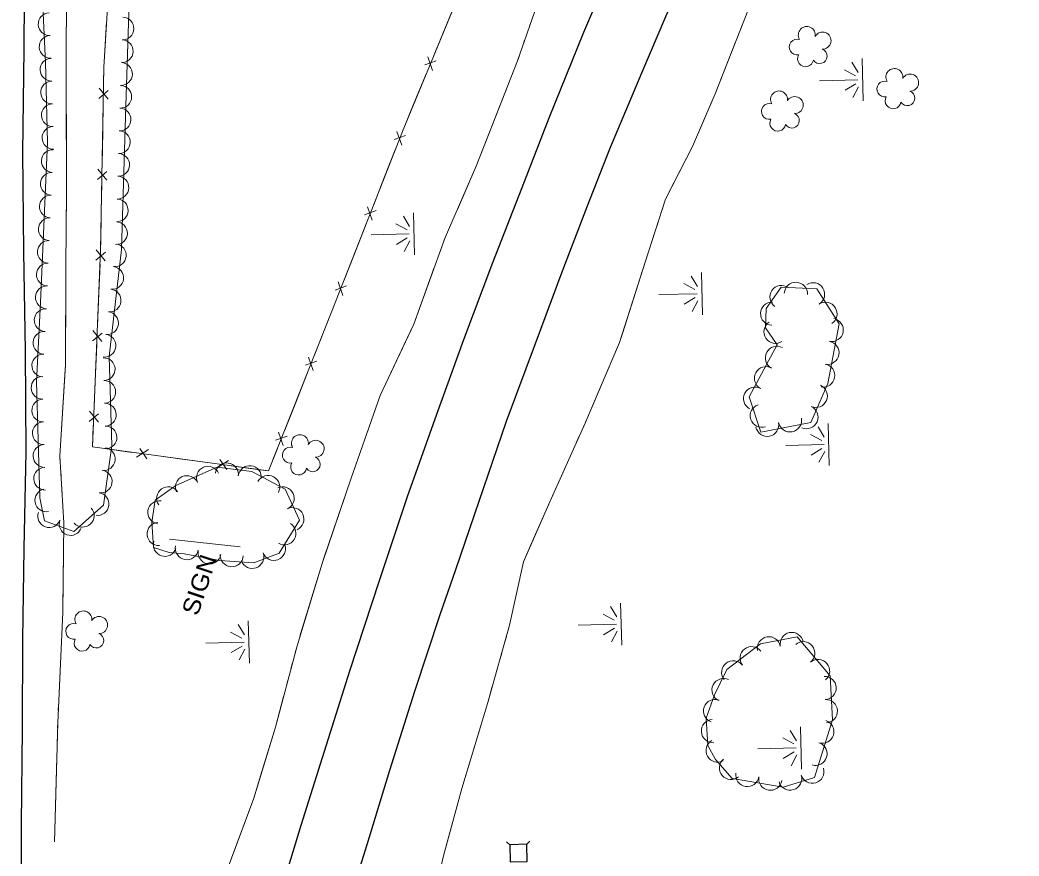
# Model space of a CAD drawing. Extents: x 296527 to 298902, y 45711 to 46924.
# Drawn here: x 297707.6 to 298057.5, y 46436.3 to 46729.1 of the extents above; entities that cross this region are included whole.
import ezdxf

# ---------------------------------------------------------------- set-up
doc = ezdxf.new("R2010")
doc.units = 0
doc.header["$LTSCALE"] = 2.4
for name, color, linetype, lineweight in [('11', 7, 'Continuous', 25), ('14', 7, 'Continuous', 13), ('15', 7, 'Continuous', 13), ('18', 7, 'Continuous', 13), ('19', 7, 'Continuous', 13), ('21', 7, 'Continuous', 25)]:
    doc.layers.add(name, color=color, linetype=linetype, lineweight=lineweight)

msp = doc.modelspace()

# ---------------------------------------------------------------- linework, layer by layer
at = {"layer": '11'}
for points in [[(297708.054, 46412.102), (297708.117, 46447.507), (297708.458, 46480.899), (297708.518, 46512.123), (297709.002, 46543.958), (297709.761, 46577.896), (297709.478, 46613.197), (297708.972, 46647.846), (297708.569, 46682.607), (297709.017, 46718.762), (297709.283, 46754.715), (297709.666, 46803.389), (297708.727, 46849.227), (297708.272, 46892.372), (297707.575, 46911.798)], [(297797.637, 46419.407), (297806.038, 46447.108), (297823.092, 46501.139), (297833.508, 46532.828), (297843.333, 46562.228), (297853.578, 46590.979), (297863.061, 46617.192), (297873.203, 46644.121), (297883.41, 46670.443), (297892.882, 46694.741), (297905.062, 46724.82), (297915.884, 46750.233), (297925.772, 46772.377), (297936.243, 46795.47), (297946.994, 46818.695), (297958.748, 46842.839), (297969.032, 46863.808), (297980.865, 46887.359), (297993.929, 46912.343)], [(297820.298, 46412.015), (297829.138, 46440.368), (297837.156, 46466.412), (297845.87, 46494.028), (297854.78, 46520.851), (297860.274, 46536.633), (297868.345, 46560.521), (297877.908, 46588.617), (297888.074, 46615.761), (297897.508, 46640.842), (297906.311, 46664.015), (297914.149, 46683.92), (297925.308, 46710.547), (297936.475, 46736.675), (297947.217, 46761.093), (297957.424, 46783.747), (297966.64, 46803.53), (297977.44, 46826.166), (297989.604, 46851.228), (298001.839, 46875.002), (298013.165, 46896.864), (298019.649, 46909.369)]]:
    msp.add_lwpolyline(points, dxfattribs=at)
at = {"layer": '14'}
msp.add_line((297759.966, 46547.257), (297784.646, 46544.522), dxfattribs=at)
at = {"layer": '15'}
for p, q in [((297860.726, 46736.553), (297856.338, 46725.929)), ((297737.293, 46718.32), (297737.912, 46728.41)), ((297856.338, 46725.929), (297852.478, 46716.586)), ((297853.37, 46714.756), (297849.311, 46713.362)), ((297850.397, 46716.171), (297851.995, 46711.428)), ((297849.927, 46710.409), (297845.538, 46699.785)), ((297735.224, 46701.532), (297738.492, 46704.315)), ((297738.509, 46701.303), (297735.286, 46705.133)), ((297736.549, 46690.048), (297736.723, 46700.156)), ((297736.35, 46678.555), (297736.549, 46690.048)), ((297842.606, 46688.628), (297838.572, 46687.16)), ((297839.608, 46689.989), (297841.291, 46685.275)), ((297839.241, 46684.219), (297835.045, 46673.519)), ((297734.735, 46673.25), (297738.004, 46676.033)), ((297738.021, 46673.02), (297734.798, 46676.851)), ((297736.06, 46661.765), (297736.235, 46671.873)), ((297835.045, 46673.519), (297831.354, 46664.107)), ((297735.862, 46650.273), (297736.06, 46661.765)), ((297832.278, 46662.294), (297828.245, 46660.827)), ((297829.28, 46663.655), (297830.964, 46658.941)), ((297828.914, 46657.886), (297824.717, 46647.185)), ((297734.162, 46645.008), (297737.498, 46647.709)), ((297737.44, 46644.697), (297734.313, 46648.606)), ((297824.717, 46647.185), (297821.026, 46637.773)), ((297735.202, 46633.494), (297735.627, 46643.595)), ((297818.952, 46637.322), (297820.636, 46632.608)), ((297734.719, 46622.01), (297735.202, 46633.494)), ((297821.951, 46635.96), (297817.917, 46634.493)), ((297732.974, 46616.746), (297736.31, 46619.447)), ((297736.252, 46616.436), (297733.125, 46620.344)), ((297814.365, 46620.861), (297810.638, 46611.464)), ((297734.014, 46605.233), (297734.439, 46615.333)), ((297811.556, 46609.647), (297807.516, 46608.195)), ((297808.563, 46611.02), (297810.228, 46606.299)), ((297733.531, 46593.748), (297734.014, 46605.233)), ((297808.174, 46605.252), (297803.936, 46594.567)), ((297803.936, 46594.567), (297800.209, 46585.17)), ((297731.786, 46588.485), (297735.122, 46591.186)), ((297735.064, 46588.174), (297731.937, 46592.083)), ((297798.133, 46584.726), (297799.799, 46580.006)), ((297801.127, 46583.353), (297797.087, 46581.901)), ((297746.894, 46577.666), (297735.505, 46579.213)), ((297752.587, 46578.675), (297748.405, 46575.924)), ((297751.973, 46575.439), (297749.594, 46579.011)), ((297763.534, 46575.406), (297753.516, 46576.766)), ((297774.923, 46573.859), (297763.534, 46575.406)), ((297780.616, 46574.867), (297776.434, 46572.117)), ((297780.002, 46571.632), (297777.623, 46575.204)), ((297791.563, 46571.599), (297781.545, 46572.959))]:
    msp.add_line(p, q, dxfattribs=at)
for points in [[(297934.044, 46907.735), (297918.048, 46878.585), (297891.783, 46819.963), (297869.421, 46757.602), (297841.737, 46690.583), (297816.848, 46627.12), (297794.659, 46571.178), (297732.935, 46579.562), (297735.83, 46648.429), (297736.937, 46712.527), (297742.759, 46807.329), (297763.72, 46870.169), (297779.778, 46909.61)], [(297736.839, 46706.837), (297736.937, 46712.527), (297737.293, 46718.32)], [(297845.538, 46699.785), (297841.737, 46690.583), (297841.681, 46690.441)], [(297818.586, 46631.552), (297816.848, 46627.12), (297814.365, 46620.861)], [(297735.505, 46579.213), (297732.935, 46579.562), (297733.251, 46587.072)], [(297797.745, 46578.958), (297794.659, 46571.178), (297791.563, 46571.599)]]:
    msp.add_lwpolyline(points, dxfattribs=at)
at = {"layer": '18'}
msp.add_lwpolyline([(297715.157, 46743.741), (297716.466, 46714.217), (297717.27, 46686.227), (297714.814, 46630.091), (297713.348, 46602.368), (297714.48, 46561.723), (297716.124, 46553.675), (297726.458, 46549.955), (297736.806, 46559.159), (297739.698, 46580.012), (297738.839, 46611.176), (297743.109, 46648.653), (297744.694, 46699.054), (297746.756, 46764.188)], dxfattribs=at)
for points in [[(297968.874, 46608.203), (297962.933, 46597.057), (297967.043, 46584.695), (297984.533, 46588.145), (297990.494, 46601.722), (297994.426, 46622.654), (297986.667, 46634.881), (297974.141, 46635.559), (297968.92, 46628.084), (297968.711, 46621.238), (297972.702, 46615.306)], [(297777.565, 46539.807), (297789.485, 46539.001), (297798.391, 46542.316), (297805.491, 46553.88), (297800.419, 46564.758), (297788.808, 46570.987), (297776.645, 46572.449), (297762.2, 46566.067), (297754.932, 46560.969), (297753.712, 46553.163), (297754.359, 46544.352), (297759.819, 46542.573), (297765.037, 46542.16)], [(297965.982, 46461.948), (297974.902, 46460.469), (297985.848, 46463.85), (297992.08, 46484.028), (297991.285, 46499.409), (297979.802, 46513.094), (297966.908, 46510.63), (297955.126, 46501.583), (297950.792, 46492.764), (297947.836, 46484.534), (297948.487, 46474.959), (297951.182, 46470.162), (297956.999, 46463.433)]]:
    msp.add_lwpolyline(points, close=True, dxfattribs=at)
for centre, radius, start, end in [((297717.959, 46727.594), 3.982, 92.54631, 272.53099), ((297743.464, 46726.059), 3.982, 268.19441, 88.17909), ((297718.312, 46719.639), 3.982, 92.54631, 272.53099), ((297983.135, 46723.798), 2.974, 349.94487, 211.17875), ((297988.651, 46721.838), 2.975, 267.59569, 150.56896), ((297743.212, 46718.1), 3.982, 268.19441, 88.17909), ((297979.775, 46719.604), 2.777, 72.91576, 280.68875), ((297982.691, 46715.467), 2.783, 149.59278, 350.60382), ((297987.644, 46716.408), 2.611, 212.30092, 70.23353), ((297718.625, 46711.65), 3.982, 91.65301, 271.63768), ((297742.96, 46710.142), 3.982, 268.19441, 88.17909), ((298013.814, 46709.084), 2.974, 349.94487, 211.17875), ((298019.33, 46707.124), 2.975, 267.59569, 150.56896), ((297718.853, 46703.691), 3.982, 91.65301, 271.63768), ((297742.708, 46702.183), 3.982, 268.19441, 88.17909), ((298010.454, 46704.89), 2.777, 72.91576, 280.68875), ((297973.398, 46701.232), 2.974, 349.94487, 211.17875), ((298018.323, 46701.694), 2.611, 212.30092, 70.23353), ((297719.082, 46695.731), 3.982, 91.65301, 271.63768), ((297970.038, 46697.038), 2.777, 72.91576, 280.68875), ((297978.914, 46699.272), 2.975, 267.59569, 150.56896), ((298013.37, 46700.753), 2.783, 149.59278, 350.60382), ((297742.457, 46694.224), 3.982, 268.20643, 88.19111), ((297977.907, 46693.842), 2.611, 212.30092, 70.23353), ((297972.954, 46692.901), 2.783, 149.59278, 350.60382), ((297719.311, 46687.772), 3.982, 91.65301, 271.63768), ((297742.207, 46686.265), 3.982, 268.20643, 88.19111), ((297719.069, 46679.665), 3.982, 87.50252, 267.48719), ((297741.956, 46678.306), 3.982, 268.20643, 88.19111), ((297718.721, 46671.71), 3.982, 87.50252, 267.48719), ((297741.706, 46670.347), 3.982, 268.20643, 88.19111), ((297718.373, 46663.755), 3.982, 87.50252, 267.48719), ((297741.456, 46662.389), 3.982, 268.20643, 88.19111), ((297718.025, 46655.8), 3.982, 87.50252, 267.48719), ((297741.206, 46654.43), 3.982, 268.20643, 88.19111), ((297717.677, 46647.845), 3.982, 87.50252, 267.48719), ((297740.784, 46646.655), 3.982, 263.50761, 83.49229), ((297717.329, 46639.89), 3.982, 87.50252, 267.48719), ((297739.882, 46638.743), 3.982, 263.50761, 83.49229), ((297974.271, 46632.04), 4.054, 55.07484, 235.05952), ((297979.315, 46633.154), 4.054, 356.90941, 176.89409), ((297985.336, 46633.019), 4.054, 302.40602, 122.3907), ((297716.981, 46631.935), 3.982, 87.50252, 267.48719), ((297738.981, 46630.832), 3.982, 263.50761, 83.49229), ((297970.986, 46626.22), 4.054, 88.25904, 268.24371), ((297989.68, 46626.174), 4.054, 302.40602, 122.3907), ((297716.577, 46623.963), 3.982, 86.98066, 266.96534), ((297738.08, 46622.92), 3.982, 263.50761, 83.49229), ((297972.179, 46619.885), 4.054, 123.94, 303.92467), ((297991.862, 46620.498), 4.054, 259.36884, 79.35351), ((297716.156, 46616.012), 3.982, 86.98066, 266.96534), ((297737.178, 46615.009), 3.982, 263.50761, 83.49229), ((297990.365, 46612.53), 4.054, 259.36884, 79.35351), ((297715.736, 46608.06), 3.982, 86.98066, 266.96534), ((297972.665, 46610.764), 4.054, 61.68623, 241.6709), ((297736.875, 46606.778), 3.982, 271.58656, 91.57123), ((297988.869, 46604.562), 4.054, 259.36884, 79.35351), ((297968.84, 46603.627), 4.054, 61.94932, 241.93399), ((297715.491, 46600.274), 3.982, 91.60299, 271.58767), ((297737.095, 46598.818), 3.982, 271.58656, 91.57123), ((297986.294, 46597.433), 4.054, 246.30372, 66.2884), ((297965.026, 46596.473), 4.054, 61.94932, 241.93399), ((297715.713, 46592.315), 3.982, 91.60299, 271.58767), ((297737.314, 46590.858), 3.982, 271.58656, 91.57123), ((297967.356, 46590.479), 4.054, 108.39811, 288.38278), ((297983.034, 46590.01), 4.054, 246.30372, 66.2884), ((297715.935, 46584.355), 3.982, 91.60299, 271.58767), ((297969.299, 46587.303), 4.054, 191.16632, 11.151), ((297977.253, 46588.872), 4.054, 191.16632, 11.151), ((297737.534, 46582.899), 3.982, 271.58656, 91.57123), ((297805.606, 46580.873), 2.974, 349.94487, 211.17875), ((297716.156, 46576.395), 3.982, 91.60299, 271.58767), ((297811.122, 46578.913), 2.975, 267.59569, 150.56896), ((297736.944, 46575.328), 3.982, 262.11196, 82.09663), ((297802.246, 46576.679), 2.777, 72.91576, 280.68875), ((297780.026, 46569.909), 4.047, 353.15356, 173.13824), ((297805.162, 46572.542), 2.783, 149.59278, 350.60382), ((297810.115, 46573.483), 2.611, 212.30092, 70.23353), ((297716.378, 46568.436), 3.982, 91.60299, 271.58767), ((297735.851, 46567.441), 3.982, 262.11196, 82.09663), ((297773.446, 46568.72), 4.047, 23.84416, 203.82884), ((297788.061, 46568.944), 4.047, 353.15356, 173.13824), ((297794.499, 46565.53), 4.047, 331.79526, 151.77994), ((297766.043, 46565.449), 4.047, 23.84416, 203.82884), ((297716.783, 46560.861), 3.982, 101.55288, 281.53756), ((297734.757, 46559.554), 3.982, 262.11196, 82.09663), ((297759.465, 46561.561), 4.047, 35.05467, 215.03935), ((297799.56, 46561.587), 4.047, 295.00552, 114.9902), ((297756.401, 46556.648), 4.047, 81.12476, 261.10944), ((297717.821, 46555.279), 3.982, 160.20996, 340.19464), ((297729.553, 46555.497), 3.982, 221.65907, 41.64374), ((297802.98, 46554.252), 4.047, 295.00552, 114.9902), ((297725.313, 46552.582), 3.982, 160.20996, 340.19464), ((297756.134, 46549.095), 4.047, 94.20741, 274.19208), ((297800.183, 46549.283), 4.047, 238.4588, 58.44348), ((297758.336, 46545.284), 4.047, 161.9608, 341.94548), ((297796.511, 46543.876), 4.047, 200.42398, 20.40866), ((297766.026, 46544.129), 4.047, 169.37034, 349.35501), ((297773.98, 46542.636), 4.047, 169.37034, 349.35501), ((297781.746, 46541.647), 4.047, 176.13936, 356.12403), ((297788.927, 46541.053), 4.047, 200.42398, 20.40866), ((297729.769, 46519.16), 2.974, 349.94487, 211.17875), ((297726.409, 46514.966), 2.777, 72.91576, 280.68875), ((297735.285, 46517.2), 2.975, 267.59569, 150.56896), ((297734.278, 46511.77), 2.611, 212.30092, 70.23353), ((297977.859, 46510.555), 4.067, 10.82626, 190.81094), ((297729.325, 46510.829), 2.783, 149.59278, 350.60382), ((297969.87, 46509.029), 4.067, 10.82626, 190.81094), ((297981.866, 46507.322), 4.067, 310.00747, 129.99215), ((297963.822, 46505.577), 4.067, 37.5271, 217.51178), ((297957.371, 46500.623), 4.067, 37.5271, 217.51178), ((297987.094, 46501.092), 4.067, 310.00747, 129.99215), ((297953.977, 46494.418), 4.067, 63.83636, 243.82104), ((297989.373, 46495.154), 4.067, 272.96648, 92.95116), ((297951.023, 46487.109), 4.067, 70.25071, 250.23538), ((297989.793, 46487.032), 4.067, 272.96648, 92.95116), ((297950.274, 46480.056), 4.067, 93.89719, 273.88187), ((297988.566, 46479.864), 4.067, 252.84429, 72.82897), ((297951.895, 46473.239), 4.067, 119.33535, 299.32003), ((297986.166, 46472.093), 4.067, 252.84429, 72.82897), ((297956.586, 46467.166), 4.067, 130.85, 310.83468), ((297962.317, 46464.711), 4.067, 170.62086, 350.60554), ((297977.292, 46463.435), 4.067, 197.17253, 17.15721), ((297985.063, 46465.835), 4.067, 197.17253, 17.15721), ((297970.343, 46463.383), 4.067, 170.59326, 350.57794)]:
    msp.add_arc(centre, radius, start, end, dxfattribs=at)
at = {"layer": '19'}
for p, q in [((297723.824, 46726.592), (297723.833, 46728.639)), ((297885.628, 46725.735), (297886.284, 46727.617)), ((297959.775, 46725.429), (297960.515, 46727.307)), ((297723.797, 46720.449), (297723.806, 46722.497)), ((297883.661, 46720.087), (297884.317, 46721.97)), ((297998.961, 46714.293), (298001.144, 46710.663)), ((298002.882, 46700.749), (298002.506, 46715.539)), ((298000.238, 46709.539), (297996.333, 46711.641)), ((297987.628, 46707.789), (298001.044, 46708.129)), ((298000.309, 46706.735), (297996.516, 46704.438)), ((297999.276, 46701.922), (298001.271, 46705.659)), ((297932.448, 46662.552), (297933.074, 46664.471)), ((297845.768, 46646.788), (297845.392, 46661.578)), ((297843.124, 46655.578), (297839.219, 46657.68)), ((297841.847, 46660.332), (297844.03, 46656.702)), ((297858.382, 46657.224), (297859.178, 46659.051)), ((297930.569, 46656.795), (297931.195, 46658.714)), ((297830.514, 46653.828), (297843.93, 46654.168)), ((297723.72, 46650.869), (297723.741, 46652.913)), ((297843.195, 46652.774), (297839.402, 46650.477)), ((297842.162, 46647.961), (297844.157, 46651.698)), ((297928.689, 46651.039), (297929.316, 46652.958)), ((297723.654, 46644.737), (297723.676, 46646.781)), ((297854.036, 46646.087), (297854.714, 46647.962)), ((297723.615, 46638.6), (297723.624, 46640.646)), ((297946.592, 46625.843), (297946.216, 46640.633)), ((297943.948, 46634.633), (297940.043, 46636.735)), ((297942.671, 46639.387), (297944.854, 46635.757)), ((297931.338, 46632.883), (297944.754, 46633.223)), ((297944.019, 46631.829), (297940.226, 46629.532)), ((297942.986, 46627.016), (297944.981, 46630.753)), ((297991.013, 46573.019), (297990.637, 46587.809)), ((297828.725, 46583.3), (297829.39, 46585.179)), ((297988.369, 46581.809), (297984.464, 46583.911)), ((297987.092, 46586.563), (297989.275, 46582.933)), ((297902.486, 46581.198), (297903.31, 46583.041)), ((297975.759, 46580.059), (297989.175, 46580.399)), ((297826.727, 46577.664), (297827.393, 46579.543)), ((297900.016, 46575.669), (297900.84, 46577.512)), ((297988.44, 46579.005), (297984.647, 46576.708)), ((297987.407, 46574.192), (297989.402, 46577.929)), ((297824.73, 46572.028), (297825.396, 46573.907)), ((297721.965, 46569.082), (297721.838, 46571.123)), ((297814.089, 46540.909), (297823.402, 46568.27)), ((297722.347, 46562.957), (297722.22, 46564.999)), ((297722.729, 46556.833), (297722.602, 46558.874)), ((297722.631, 46523.086), (297722.965, 46552.749)), ((297918.317, 46510.115), (297917.941, 46524.905)), ((297915.673, 46518.905), (297911.768, 46521.007)), ((297914.396, 46523.659), (297916.579, 46520.029)), ((297783.984, 46517.391), (297786.167, 46513.761)), ((297787.905, 46503.847), (297787.529, 46518.637)), ((297903.063, 46517.155), (297916.479, 46517.495)), ((297785.261, 46512.637), (297781.356, 46514.739)), ((297915.744, 46516.101), (297911.951, 46513.804)), ((297914.711, 46511.288), (297916.706, 46515.025)), ((297772.651, 46510.887), (297786.067, 46511.227)), ((297877.378, 46511.207), (297877.927, 46513.15)), ((297785.332, 46509.833), (297781.539, 46507.536)), ((297784.299, 46505.02), (297786.294, 46508.757)), ((297803.981, 46507.526), (297804.494, 46509.452)), ((297875.732, 46505.379), (297876.281, 46507.322)), ((297802.441, 46501.747), (297802.954, 46503.674)), ((297874.086, 46499.552), (297874.635, 46501.494)), ((297800.902, 46495.969), (297801.415, 46497.895)), ((297720.983, 46487.311), (297721.08, 46489.355)), ((297977.346, 46480.322), (297979.529, 46476.692)), ((297981.267, 46466.778), (297980.891, 46481.568)), ((297720.558, 46475.038), (297720.614, 46477.084)), ((297978.623, 46475.568), (297974.718, 46477.67)), ((297966.013, 46473.818), (297979.429, 46474.158)), ((297978.694, 46472.764), (297974.901, 46470.467)), ((297977.661, 46467.951), (297979.656, 46471.688)), ((297719.624, 46441.276), (297720.445, 46470.946))]:
    msp.add_line(p, q, dxfattribs=at)
for points in [[(297849.168, 46407.743), (297855.933, 46436.406), (297862.339, 46459.994), (297871.416, 46490.098), (297879.057, 46517.15), (297883.894, 46539.3), (297893.627, 46561.368), (297905.47, 46587.876), (297917.581, 46616.135), (297926.493, 46644.311), (297933.689, 46666.354), (297943.064, 46684.718), (297951.029, 46703.202), (297962.693, 46732.843), (297969.576, 46750.509), (297979.206, 46766.525), (297992.799, 46783.396), (298003.624, 46804.221), (298020.877, 46837.356), (298033.907, 46864.644), (298048.564, 46892.117), (298057.459, 46909.387)], [(297727.661, 46234.355), (297732.98, 46260.083), (297738.903, 46291.249), (297745.297, 46315.358), (297756.148, 46347.424), (297765.976, 46376.737), (297771.06, 46400.488), (297779.797, 46430.522), (297789.42, 46456.6), (297797.023, 46481.408), (297804.603, 46509.862), (297813.358, 46538.762), (297823.513, 46568.595), (297833.773, 46597.545), (297845.531, 46622.563), (297856.504, 46652.912), (297867.391, 46677.903), (297881.799, 46714.74), (297897.082, 46758.62), (297911.1, 46787.728), (297927.574, 46820.51), (297941.355, 46857.021), (297955.912, 46885.019), (297969.251, 46907.237)], [(297719.624, 46441.276), (297720.777, 46482.963), (297722.616, 46521.753), (297722.968, 46553.002), (297721.513, 46576.337), (297723.475, 46608.269), (297723.635, 46642.928), (297723.906, 46668.367), (297723.733, 46705.736), (297723.916, 46747.538), (297725.109, 46811.661), (297724.234, 46850.444)], [(297947.301, 46694.55), (297951.029, 46703.202), (297958.297, 46721.672)], [(297723.821, 46686.668), (297723.733, 46705.736), (297723.779, 46716.355)], [(297871.881, 46689.383), (297881.799, 46714.74), (297882.35, 46716.322)], [(297934.624, 46668.185), (297943.064, 46684.718), (297947.301, 46694.55)], [(297860.771, 46662.706), (297867.391, 46677.903), (297871.881, 46689.383)], [(297723.785, 46657.001), (297723.906, 46668.367), (297723.821, 46686.668)], [(297856.07, 46651.711), (297856.504, 46652.912), (297856.79, 46653.569)], [(297918.583, 46619.302), (297926.493, 46644.311), (297927.436, 46647.201)], [(297842.182, 46615.436), (297845.531, 46622.563), (297852.681, 46642.338)], [(297723.264, 46604.835), (297723.475, 46608.269), (297723.596, 46634.506)], [(297907.36, 46592.285), (297917.581, 46616.135), (297918.583, 46619.302)], [(297830.722, 46588.936), (297833.773, 46597.545), (297842.182, 46615.436)], [(297721.584, 46575.206), (297721.513, 46576.337), (297723.264, 46604.835)], [(297904.957, 46586.727), (297905.47, 46587.876), (297905.769, 46588.575)], [(297886.508, 46545.226), (297893.627, 46561.368), (297898.369, 46571.983)], [(297879.024, 46517.035), (297879.057, 46517.15), (297883.894, 46539.3), (297886.508, 46545.226)], [(297805.636, 46513.271), (297813.358, 46538.762), (297814.089, 46540.909)], [(297721.274, 46493.444), (297722.616, 46521.753), (297722.631, 46523.086)], [(297864.637, 46467.614), (297871.416, 46490.098), (297872.989, 46495.666)], [(297791.801, 46464.37), (297797.023, 46481.408), (297799.876, 46492.117)], [(297720.728, 46481.176), (297720.777, 46482.963), (297720.789, 46483.222)], [(297856.754, 46439.428), (297862.339, 46459.994), (297864.637, 46467.614)], [(297782.227, 46437.108), (297789.42, 46456.6), (297791.801, 46464.37)]]:
    msp.add_lwpolyline(points, dxfattribs=at)
at = {"layer": '21'}
for p, q in [((297879.105, 46440.272), (297878.018, 46441.305)), ((297886.136, 46441.511), (297885.102, 46440.425))]:
    msp.add_line(p, q, dxfattribs=at)
msp.add_lwpolyline([(297885.254, 46434.426), (297885.102, 46440.425), (297879.105, 46440.272), (297879.257, 46434.273)], close=True, dxfattribs=at)

# ---------------------------------------------------------------- texts
at = {"layer": '14', "width": 1.1}
msp.add_text('SIGN', height=6, rotation=71.521, dxfattribs=at).set_placement((297769.807, 46520.098))

doc.saveas('drawing.dxf')
